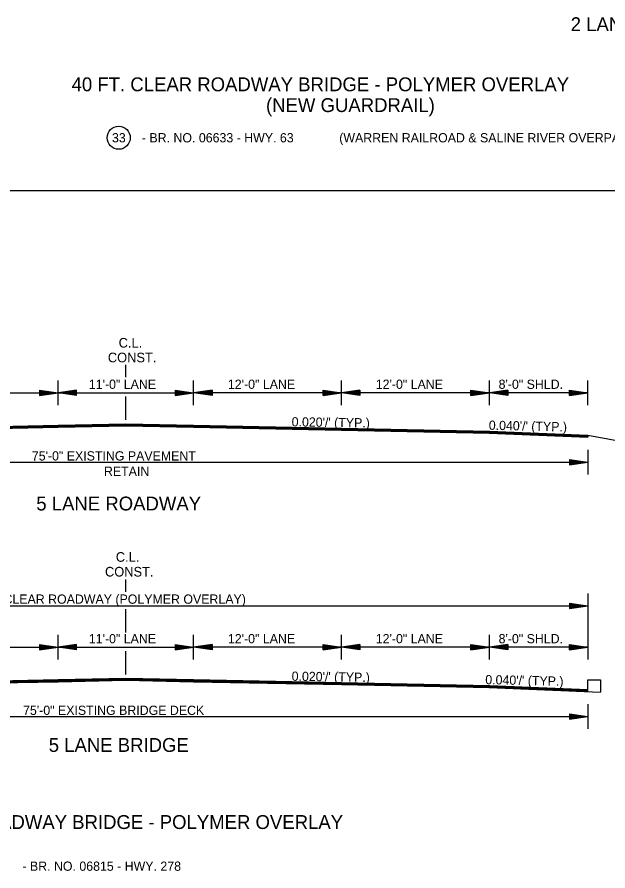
# Model space of a CAD drawing. Extents: x 545241 to 1930787, y -1971772 to 596640.
# Drawn here: x 547171 to 547650, y -1963938 to -1963245 of the extents above; entities that cross this region are included whole.
import ezdxf

# ---------------------------------------------------------------- set-up
doc = ezdxf.new("R2010")
doc.units = 0
doc.layers.add('R_Border', color=7, linetype='Continuous')
doc.layers.add('R_Draft', color=7, linetype='Continuous')

msp = doc.modelspace()

# ---------------------------------------------------------------- linework, layer by layer
at = {"layer": 'R_Border'}
for p, q in [((546745.07, -1963386.13), (547773.02, -1963386.13)), ((547634.04, -1963783.08), (547644.21, -1963783.08)), ((547634.04, -1963792.49), (547634.04, -1963783.08)), ((547644.21, -1963783.08), (547644.21, -1963793.07))]:
    msp.add_line(p, q, dxfattribs=at)
msp.add_circle((547253.23, -1963343.4), 9.34, dxfattribs=at)
at = {"layer": 'R_Draft'}
for p, q in [((547259.04, -1963537.63), (547259.04, -1963527.63)), ((547204.04, -1963560.29), (547204.04, -1963540.39)), ((547314.04, -1963560.29), (547314.04, -1963540.39)), ((547434.04, -1963560.29), (547434.04, -1963540.39)), ((547554.04, -1963560.29), (547554.04, -1963540.39)), ((547634.04, -1963560.29), (547634.04, -1963540.29)), ((547189.04, -1963548.04), (547204.04, -1963550.29)), ((547189.04, -1963548.04), (547189.04, -1963552.54)), ((547189.04, -1963548.41), (547201.54, -1963550.29)), ((547189.04, -1963548.79), (547198.96, -1963550.29)), ((547189.04, -1963549.17), (547196.46, -1963550.29)), ((547189.04, -1963549.56), (547193.92, -1963550.29)), ((547189.04, -1963549.93), (547191.41, -1963550.29)), ((547219.04, -1963548.04), (547204.04, -1963550.29)), ((547219.04, -1963548.41), (547206.55, -1963550.29)), ((547219.04, -1963548.79), (547209.13, -1963550.29)), ((547219.04, -1963549.17), (547211.63, -1963550.29)), ((547219.04, -1963549.55), (547214.17, -1963550.29)), ((547219.04, -1963549.93), (547216.67, -1963550.29)), ((547219.04, -1963552.54), (547219.04, -1963548.04)), ((547299.04, -1963548.04), (547314.04, -1963550.29)), ((547299.04, -1963548.04), (547299.04, -1963552.54)), ((547299.04, -1963548.41), (547311.54, -1963550.29)), ((547299.04, -1963548.79), (547308.96, -1963550.29)), ((547299.04, -1963549.17), (547306.46, -1963550.29)), ((547299.04, -1963549.56), (547303.92, -1963550.29)), ((547299.04, -1963549.93), (547301.41, -1963550.29)), ((547329.04, -1963548.04), (547314.04, -1963550.29)), ((547329.04, -1963548.41), (547316.55, -1963550.29)), ((547329.04, -1963548.79), (547319.13, -1963550.29)), ((547329.04, -1963549.17), (547321.63, -1963550.29)), ((547329.04, -1963549.56), (547324.17, -1963550.29)), ((547329.04, -1963549.93), (547326.67, -1963550.29)), ((547329.04, -1963548.04), (547329.04, -1963552.54)), ((547419.04, -1963548.04), (547434.04, -1963550.29)), ((547419.04, -1963552.54), (547419.04, -1963548.04)), ((547419.04, -1963548.41), (547431.54, -1963550.29)), ((547419.04, -1963548.79), (547428.96, -1963550.29)), ((547419.04, -1963549.17), (547426.46, -1963550.29)), ((547419.04, -1963549.55), (547423.92, -1963550.29)), ((547419.04, -1963549.93), (547421.41, -1963550.29)), ((547449.04, -1963548.04), (547434.04, -1963550.29)), ((547449.04, -1963548.41), (547436.55, -1963550.29)), ((547449.04, -1963548.79), (547439.13, -1963550.29)), ((547449.04, -1963549.17), (547441.63, -1963550.29)), ((547449.04, -1963549.56), (547444.17, -1963550.29)), ((547449.04, -1963549.93), (547446.67, -1963550.29)), ((547449.04, -1963548.04), (547449.04, -1963552.54)), ((547539.04, -1963548.04), (547554.04, -1963550.29)), ((547539.04, -1963552.54), (547539.04, -1963548.04)), ((547539.04, -1963548.41), (547551.54, -1963550.29)), ((547539.04, -1963548.79), (547548.96, -1963550.29)), ((547539.04, -1963549.17), (547546.46, -1963550.29)), ((547539.04, -1963549.55), (547543.92, -1963550.29)), ((547539.04, -1963549.93), (547541.41, -1963550.29)), ((547569.04, -1963548.04), (547554.04, -1963550.29)), ((547569.04, -1963548.41), (547556.55, -1963550.29)), ((547569.04, -1963548.79), (547559.13, -1963550.29)), ((547569.04, -1963549.17), (547561.63, -1963550.29)), ((547569.04, -1963549.56), (547564.17, -1963550.29)), ((547569.04, -1963549.93), (547566.67, -1963550.29)), ((547569.04, -1963548.04), (547569.04, -1963552.54)), ((547619.04, -1963548.04), (547634.04, -1963550.29)), ((547619.04, -1963552.54), (547619.04, -1963548.04)), ((547619.04, -1963548.41), (547631.54, -1963550.29)), ((547619.04, -1963548.79), (547628.96, -1963550.29)), ((547619.04, -1963549.17), (547626.46, -1963550.29)), ((547619.04, -1963549.55), (547623.92, -1963550.29)), ((547619.04, -1963549.93), (547621.41, -1963550.29)), ((547084.04, -1963550.29), (547204.04, -1963550.29)), ((547189.04, -1963552.54), (547204.04, -1963550.29)), ((547189.04, -1963551.02), (547193.92, -1963550.29)), ((547189.04, -1963551.78), (547198.96, -1963550.29)), ((547189.04, -1963552.16), (547201.54, -1963550.29)), ((547189.04, -1963551.4), (547196.46, -1963550.29)), ((547189.04, -1963550.64), (547191.41, -1963550.29)), ((547204.04, -1963550.29), (547314.04, -1963550.29)), ((547219.04, -1963552.54), (547204.04, -1963550.29)), ((547219.04, -1963552.16), (547206.55, -1963550.29)), ((547219.04, -1963551.78), (547209.13, -1963550.29)), ((547219.04, -1963551.4), (547211.63, -1963550.29)), ((547219.04, -1963551.01), (547214.17, -1963550.29)), ((547219.04, -1963550.64), (547216.67, -1963550.29)), ((547259.04, -1963572.34), (547259.04, -1963553.4)), ((547299.04, -1963552.54), (547314.04, -1963550.29)), ((547299.04, -1963551.02), (547303.92, -1963550.29)), ((547299.04, -1963551.78), (547308.96, -1963550.29)), ((547299.04, -1963552.16), (547311.54, -1963550.29)), ((547299.04, -1963551.4), (547306.46, -1963550.29)), ((547299.04, -1963550.64), (547301.41, -1963550.29)), ((547434.04, -1963550.29), (547314.04, -1963550.29)), ((547329.04, -1963552.54), (547314.04, -1963550.29)), ((547329.04, -1963552.16), (547316.55, -1963550.29)), ((547329.04, -1963551.78), (547319.13, -1963550.29)), ((547329.04, -1963551.4), (547321.63, -1963550.29)), ((547329.04, -1963551.02), (547324.17, -1963550.29)), ((547329.04, -1963550.64), (547326.67, -1963550.29)), ((547419.04, -1963552.54), (547434.04, -1963550.29)), ((547419.04, -1963551.01), (547423.92, -1963550.29)), ((547419.04, -1963551.78), (547428.96, -1963550.29)), ((547419.04, -1963552.16), (547431.54, -1963550.29)), ((547419.04, -1963551.4), (547426.46, -1963550.29)), ((547419.04, -1963550.64), (547421.41, -1963550.29)), ((547554.04, -1963550.29), (547434.04, -1963550.29)), ((547449.04, -1963552.54), (547434.04, -1963550.29)), ((547449.04, -1963552.16), (547436.55, -1963550.29)), ((547449.04, -1963551.78), (547439.13, -1963550.29)), ((547449.04, -1963551.4), (547441.63, -1963550.29)), ((547449.04, -1963551.02), (547444.17, -1963550.29)), ((547449.04, -1963550.64), (547446.67, -1963550.29)), ((547539.04, -1963552.54), (547554.04, -1963550.29)), ((547539.04, -1963551.01), (547543.92, -1963550.29)), ((547539.04, -1963551.78), (547548.96, -1963550.29)), ((547539.04, -1963552.16), (547551.54, -1963550.29)), ((547539.04, -1963551.4), (547546.46, -1963550.29)), ((547539.04, -1963550.64), (547541.41, -1963550.29)), ((547634.04, -1963550.29), (547554.04, -1963550.29)), ((547569.04, -1963552.54), (547554.04, -1963550.29)), ((547569.04, -1963552.16), (547556.55, -1963550.29)), ((547569.04, -1963551.78), (547559.13, -1963550.29)), ((547569.04, -1963551.4), (547561.63, -1963550.29)), ((547569.04, -1963551.02), (547564.17, -1963550.29)), ((547569.04, -1963550.64), (547566.67, -1963550.29)), ((547619.04, -1963552.54), (547634.04, -1963550.29)), ((547619.04, -1963551.01), (547623.92, -1963550.29)), ((547619.04, -1963551.78), (547628.96, -1963550.29)), ((547619.04, -1963552.16), (547631.54, -1963550.29)), ((547619.04, -1963551.4), (547626.46, -1963550.29)), ((547619.04, -1963550.64), (547621.41, -1963550.29)), ((547084.04, -1963578.99), (547204.04, -1963576.59)), ((547084.04, -1963579.29), (547204.04, -1963576.89)), ((547084.04, -1963579.59), (547204.04, -1963577.19)), ((547084.04, -1963579.89), (547204.04, -1963577.49)), ((547084.04, -1963580.19), (547204.04, -1963577.79)), ((547204.04, -1963576.59), (547259.04, -1963575.49)), ((547204.04, -1963576.89), (547259.04, -1963575.79)), ((547204.04, -1963577.19), (547259.04, -1963576.09)), ((547204.04, -1963577.49), (547259.04, -1963576.39)), ((547204.04, -1963577.79), (547259.04, -1963576.69)), ((547204.04, -1963578.09), (547259.04, -1963576.99)), ((547204.04, -1963578.26), (547259.04, -1963577.16)), ((547259.04, -1963575.49), (547314.04, -1963576.59)), ((547259.04, -1963575.79), (547314.04, -1963576.89)), ((547259.04, -1963576.09), (547314.04, -1963577.19)), ((547259.04, -1963576.39), (547314.04, -1963577.49)), ((547259.04, -1963576.69), (547314.04, -1963577.79)), ((547259.04, -1963576.99), (547314.04, -1963578.09)), ((547259.04, -1963577.16), (547314.04, -1963578.26)), ((547314.04, -1963576.59), (547434.04, -1963578.99)), ((547314.04, -1963576.89), (547434.04, -1963579.29)), ((547314.04, -1963577.19), (547434.04, -1963579.59)), ((547314.04, -1963577.49), (547434.04, -1963579.89)), ((547314.04, -1963577.79), (547434.04, -1963580.19)), ((547084.04, -1963580.49), (547204.04, -1963578.09)), ((547084.04, -1963580.66), (547204.04, -1963578.26)), ((547314.04, -1963578.09), (547434.04, -1963580.49)), ((547314.04, -1963578.26), (547434.04, -1963580.66)), ((547434.04, -1963578.99), (547554.04, -1963581.39)), ((547434.04, -1963579.29), (547554.04, -1963581.69)), ((547434.04, -1963579.59), (547554.04, -1963581.99)), ((547434.04, -1963579.89), (547554.04, -1963582.29)), ((547434.04, -1963580.19), (547554.04, -1963582.59)), ((547434.04, -1963580.49), (547554.04, -1963582.89)), ((547434.04, -1963580.66), (547554.04, -1963583.06)), ((547553.99, -1963583.06), (547634.04, -1963586.26)), ((547554, -1963582.89), (547634.04, -1963586.09)), ((547554.01, -1963582.59), (547634.04, -1963585.79)), ((547554.02, -1963582.29), (547634.04, -1963585.49)), ((547554.03, -1963581.69), (547634.04, -1963584.89)), ((547554.03, -1963581.99), (547634.04, -1963585.19)), ((547554.04, -1963581.39), (547634.04, -1963584.59)), ((547634.04, -1963584.59), (547634.04, -1963586.26)), ((547634.04, -1963584.59), (547734.11, -1963602.97)), ((547634.04, -1963596.63), (547634.04, -1963616.63)), ((547619.02, -1963604.3), (547634.02, -1963606.55)), ((547619.02, -1963604.3), (547619.02, -1963608.8)), ((547619.02, -1963604.68), (547631.51, -1963606.55)), ((547619.02, -1963605.06), (547628.93, -1963606.55)), ((547619.02, -1963605.43), (547626.44, -1963606.55)), ((546884.04, -1963606.55), (547634.04, -1963606.55)), ((547619.02, -1963605.82), (547623.89, -1963606.55)), ((547619.02, -1963606.2), (547621.39, -1963606.55)), ((547619.02, -1963608.8), (547634.02, -1963606.55)), ((547619.02, -1963607.29), (547623.89, -1963606.55)), ((547619.02, -1963608.04), (547628.93, -1963606.55)), ((547619.02, -1963608.43), (547631.51, -1963606.55)), ((547619.02, -1963607.67), (547626.44, -1963606.55)), ((547619.02, -1963606.9), (547621.39, -1963606.55)), ((547259.04, -1963711.67), (547259.04, -1963701.67)), ((547634.04, -1963713.15), (547634.04, -1963766.68)), ((546884.04, -1963723.15), (547634.04, -1963723.15)), ((547619.04, -1963720.9), (547634.04, -1963723.15)), ((547619.04, -1963720.9), (547619.04, -1963725.4)), ((547619.04, -1963721.27), (547631.54, -1963723.15)), ((547619.04, -1963721.65), (547628.96, -1963723.15)), ((547619.04, -1963722.03), (547626.46, -1963723.15)), ((547619.04, -1963722.42), (547623.92, -1963723.15)), ((547619.04, -1963722.79), (547621.41, -1963723.15)), ((547619.04, -1963725.4), (547634.04, -1963723.15)), ((547619.04, -1963723.88), (547623.92, -1963723.15)), ((547619.04, -1963724.64), (547628.96, -1963723.15)), ((547619.04, -1963725.02), (547631.54, -1963723.15)), ((547619.04, -1963724.26), (547626.46, -1963723.15)), ((547619.04, -1963723.5), (547621.41, -1963723.15)), ((547259.04, -1963744.67), (547259.04, -1963725.97)), ((547204.04, -1963766.68), (547204.04, -1963746.79)), ((547314.04, -1963766.68), (547314.04, -1963746.79)), ((547434.04, -1963766.68), (547434.04, -1963746.79)), ((547554.04, -1963766.68), (547554.04, -1963746.79)), ((547084.04, -1963756.68), (547204.04, -1963756.68)), ((547189.04, -1963754.43), (547204.04, -1963756.68)), ((547189.04, -1963754.43), (547189.04, -1963758.93)), ((547189.04, -1963754.81), (547201.54, -1963756.68)), ((547189.04, -1963755.19), (547198.96, -1963756.68)), ((547189.04, -1963755.57), (547196.46, -1963756.68)), ((547189.04, -1963755.96), (547193.92, -1963756.68)), ((547189.04, -1963756.33), (547191.41, -1963756.68)), ((547189.04, -1963758.93), (547204.04, -1963756.68)), ((547189.04, -1963757.42), (547193.92, -1963756.68)), ((547189.04, -1963758.18), (547198.96, -1963756.68)), ((547189.04, -1963758.56), (547201.54, -1963756.68)), ((547189.04, -1963757.8), (547196.46, -1963756.68)), ((547189.04, -1963757.04), (547191.41, -1963756.68)), ((547219.04, -1963754.43), (547204.04, -1963756.68)), ((547204.04, -1963756.68), (547314.04, -1963756.68)), ((547219.04, -1963758.93), (547204.04, -1963756.68)), ((547219.04, -1963754.81), (547206.55, -1963756.68)), ((547219.04, -1963758.56), (547206.55, -1963756.68)), ((547219.04, -1963755.19), (547209.13, -1963756.68)), ((547219.04, -1963758.18), (547209.13, -1963756.68)), ((547219.04, -1963755.57), (547211.63, -1963756.68)), ((547219.04, -1963757.8), (547211.63, -1963756.68)), ((547219.04, -1963755.95), (547214.17, -1963756.68)), ((547219.04, -1963757.41), (547214.17, -1963756.68)), ((547219.04, -1963756.33), (547216.67, -1963756.68)), ((547219.04, -1963757.04), (547216.67, -1963756.68)), ((547219.04, -1963758.93), (547219.04, -1963754.43)), ((547299.04, -1963754.43), (547314.04, -1963756.68)), ((547299.04, -1963754.43), (547299.04, -1963758.93)), ((547299.04, -1963754.81), (547311.54, -1963756.68)), ((547299.04, -1963755.19), (547308.96, -1963756.68)), ((547299.04, -1963755.57), (547306.46, -1963756.68)), ((547299.04, -1963755.96), (547303.92, -1963756.68)), ((547299.04, -1963756.33), (547301.41, -1963756.68)), ((547299.04, -1963758.93), (547314.04, -1963756.68)), ((547299.04, -1963757.42), (547303.92, -1963756.68)), ((547299.04, -1963758.18), (547308.96, -1963756.68)), ((547299.04, -1963758.56), (547311.54, -1963756.68)), ((547299.04, -1963757.8), (547306.46, -1963756.68)), ((547299.04, -1963757.04), (547301.41, -1963756.68)), ((547329.04, -1963754.43), (547314.04, -1963756.68)), ((547434.04, -1963756.68), (547314.04, -1963756.68)), ((547329.04, -1963758.93), (547314.04, -1963756.68)), ((547329.04, -1963754.81), (547316.55, -1963756.68)), ((547329.04, -1963758.56), (547316.55, -1963756.68)), ((547329.04, -1963755.19), (547319.13, -1963756.68)), ((547329.04, -1963758.18), (547319.13, -1963756.68)), ((547329.04, -1963755.57), (547321.63, -1963756.68)), ((547329.04, -1963757.8), (547321.63, -1963756.68)), ((547329.04, -1963755.96), (547324.17, -1963756.68)), ((547329.04, -1963757.42), (547324.17, -1963756.68)), ((547329.04, -1963756.33), (547326.67, -1963756.68)), ((547329.04, -1963757.04), (547326.67, -1963756.68)), ((547329.04, -1963754.43), (547329.04, -1963758.93)), ((547419.04, -1963754.43), (547434.04, -1963756.68)), ((547419.04, -1963758.93), (547419.04, -1963754.43)), ((547419.04, -1963754.81), (547431.54, -1963756.68)), ((547419.04, -1963755.19), (547428.96, -1963756.68)), ((547419.04, -1963755.57), (547426.46, -1963756.68)), ((547419.04, -1963755.95), (547423.92, -1963756.68)), ((547419.04, -1963756.33), (547421.41, -1963756.68)), ((547419.04, -1963758.93), (547434.04, -1963756.68)), ((547419.04, -1963757.41), (547423.92, -1963756.68)), ((547419.04, -1963758.18), (547428.96, -1963756.68)), ((547419.04, -1963758.56), (547431.54, -1963756.68)), ((547419.04, -1963757.8), (547426.46, -1963756.68)), ((547419.04, -1963757.04), (547421.41, -1963756.68)), ((547449.04, -1963754.43), (547434.04, -1963756.68)), ((547554.04, -1963756.68), (547434.04, -1963756.68)), ((547449.04, -1963758.93), (547434.04, -1963756.68)), ((547449.04, -1963754.81), (547436.55, -1963756.68)), ((547449.04, -1963758.56), (547436.55, -1963756.68)), ((547449.04, -1963755.19), (547439.13, -1963756.68)), ((547449.04, -1963758.18), (547439.13, -1963756.68)), ((547449.04, -1963755.57), (547441.63, -1963756.68)), ((547449.04, -1963757.8), (547441.63, -1963756.68)), ((547449.04, -1963755.96), (547444.17, -1963756.68)), ((547449.04, -1963757.42), (547444.17, -1963756.68)), ((547449.04, -1963756.33), (547446.67, -1963756.68)), ((547449.04, -1963757.04), (547446.67, -1963756.68)), ((547449.04, -1963754.43), (547449.04, -1963758.93)), ((547539.04, -1963754.43), (547554.04, -1963756.68)), ((547539.04, -1963758.93), (547539.04, -1963754.43)), ((547539.04, -1963754.81), (547551.54, -1963756.68)), ((547539.04, -1963755.19), (547548.96, -1963756.68)), ((547539.04, -1963755.57), (547546.46, -1963756.68)), ((547539.04, -1963755.95), (547543.92, -1963756.68)), ((547539.04, -1963756.33), (547541.41, -1963756.68)), ((547539.04, -1963758.93), (547554.04, -1963756.68)), ((547539.04, -1963757.41), (547543.92, -1963756.68)), ((547539.04, -1963758.18), (547548.96, -1963756.68)), ((547539.04, -1963758.56), (547551.54, -1963756.68)), ((547539.04, -1963757.8), (547546.46, -1963756.68)), ((547539.04, -1963757.04), (547541.41, -1963756.68)), ((547569.04, -1963754.43), (547554.04, -1963756.68)), ((547634.04, -1963756.68), (547554.04, -1963756.68)), ((547569.04, -1963758.93), (547554.04, -1963756.68)), ((547569.04, -1963754.81), (547556.55, -1963756.68)), ((547569.04, -1963758.56), (547556.55, -1963756.68)), ((547569.04, -1963755.19), (547559.13, -1963756.68)), ((547569.04, -1963758.18), (547559.13, -1963756.68)), ((547569.04, -1963755.57), (547561.63, -1963756.68)), ((547569.04, -1963757.8), (547561.63, -1963756.68)), ((547569.04, -1963755.96), (547564.17, -1963756.68)), ((547569.04, -1963757.42), (547564.17, -1963756.68)), ((547569.04, -1963756.33), (547566.67, -1963756.68)), ((547569.04, -1963757.04), (547566.67, -1963756.68)), ((547569.04, -1963754.43), (547569.04, -1963758.93)), ((547619.04, -1963754.43), (547634.04, -1963756.68)), ((547619.04, -1963758.93), (547619.04, -1963754.43)), ((547619.04, -1963754.81), (547631.54, -1963756.68)), ((547619.04, -1963755.19), (547628.96, -1963756.68)), ((547619.04, -1963755.57), (547626.46, -1963756.68)), ((547619.04, -1963755.95), (547623.92, -1963756.68)), ((547619.04, -1963756.33), (547621.41, -1963756.68)), ((547619.04, -1963758.93), (547634.04, -1963756.68)), ((547619.04, -1963757.41), (547623.92, -1963756.68)), ((547619.04, -1963758.18), (547628.96, -1963756.68)), ((547619.04, -1963758.56), (547631.54, -1963756.68)), ((547619.04, -1963757.8), (547626.46, -1963756.68)), ((547619.04, -1963757.04), (547621.41, -1963756.68)), ((547259.04, -1963778.74), (547259.04, -1963759.8)), ((547084.04, -1963785.39), (547204.04, -1963782.99)), ((547084.04, -1963785.69), (547204.04, -1963783.29)), ((547084.04, -1963785.99), (547204.04, -1963783.59)), ((547084.04, -1963786.29), (547204.04, -1963783.89)), ((547084.04, -1963786.59), (547204.04, -1963784.19)), ((547084.04, -1963786.89), (547204.04, -1963784.49)), ((547084.04, -1963787.06), (547204.04, -1963784.66)), ((547204.04, -1963782.99), (547259.04, -1963781.89)), ((547204.04, -1963783.29), (547259.04, -1963782.19)), ((547204.04, -1963783.59), (547259.04, -1963782.49)), ((547204.04, -1963783.89), (547259.04, -1963782.79)), ((547204.04, -1963784.19), (547259.04, -1963783.09)), ((547204.04, -1963784.49), (547259.04, -1963783.39)), ((547204.04, -1963784.66), (547259.04, -1963783.56)), ((547259.04, -1963781.89), (547314.04, -1963782.99)), ((547259.04, -1963782.19), (547314.04, -1963783.29)), ((547259.04, -1963782.49), (547314.04, -1963783.59)), ((547259.04, -1963782.79), (547314.04, -1963783.89)), ((547259.04, -1963783.09), (547314.04, -1963784.19)), ((547259.04, -1963783.39), (547314.04, -1963784.49)), ((547259.04, -1963783.56), (547314.04, -1963784.66)), ((547314.04, -1963782.99), (547434.04, -1963785.39)), ((547314.04, -1963783.29), (547434.04, -1963785.69)), ((547314.04, -1963783.59), (547434.04, -1963785.99)), ((547314.04, -1963783.89), (547434.04, -1963786.29)), ((547314.04, -1963784.19), (547434.04, -1963786.59)), ((547314.04, -1963784.49), (547434.04, -1963786.89)), ((547314.04, -1963784.66), (547434.04, -1963787.06)), ((547434.04, -1963785.39), (547554.04, -1963787.79)), ((547434.04, -1963785.69), (547554.04, -1963788.09)), ((547434.04, -1963785.99), (547554.04, -1963788.39)), ((547434.04, -1963786.29), (547554.04, -1963788.69)), ((547434.04, -1963786.59), (547554.04, -1963788.99)), ((547434.04, -1963786.89), (547554.04, -1963789.29)), ((547434.04, -1963787.06), (547554.04, -1963789.46)), ((547553.99, -1963789.46), (547644.21, -1963793.07)), ((547554, -1963789.29), (547634.04, -1963792.49)), ((547554.01, -1963788.99), (547634.04, -1963792.19)), ((547554.02, -1963788.69), (547634.04, -1963791.89)), ((547554.03, -1963788.09), (547634.04, -1963791.29)), ((547554.03, -1963788.39), (547634.04, -1963791.59)), ((547554.04, -1963787.79), (547634.04, -1963790.99)), ((547634.04, -1963803.02), (547634.04, -1963823.02)), ((546884.04, -1963812.95), (547634.04, -1963812.95)), ((547619.02, -1963810.7), (547634.02, -1963812.95)), ((547619.02, -1963810.7), (547619.02, -1963815.2)), ((547619.02, -1963811.07), (547631.51, -1963812.95)), ((547619.02, -1963811.45), (547628.93, -1963812.95)), ((547619.02, -1963811.83), (547626.44, -1963812.95)), ((547619.02, -1963812.22), (547623.89, -1963812.95)), ((547619.02, -1963812.59), (547621.39, -1963812.95)), ((547619.02, -1963815.2), (547634.02, -1963812.95)), ((547619.02, -1963813.68), (547623.89, -1963812.95)), ((547619.02, -1963814.44), (547628.93, -1963812.95)), ((547619.02, -1963814.82), (547631.51, -1963812.95)), ((547619.02, -1963814.06), (547626.44, -1963812.95)), ((547619.02, -1963813.3), (547621.39, -1963812.95))]:
    msp.add_line(p, q, dxfattribs=at)

# ---------------------------------------------------------------- texts
for s, height, p in [('2 LANE BRIDGE - RAILROAD OVERPASS', 11.25, (547620.07, -1963256.91)), ('40 FT. CLEAR ROADWAY BRIDGE - POLYMER OVERLAY', 11.25, (547214.98, -1963305.67)), ('(NEW GUARDRAIL)', 11.25, (547372.75, -1963322.54)), ('33', 7.5, (547247.74, -1963347.15)), ('- BR. NO. 06633 - HWY. 63', 7.5, (547272.03, -1963347.15)), ('(WARREN RAILROAD & SALINE RIVER OVERPASS)', 7.5, (547432.23, -1963347.15)), ('C.L.', 7.8, (547253.18, -1963513.61)), ('CONST.', 7.8, (547244.4, -1963525.57)), ('11\'-0" LANE', 7.5, (547228.98, -1963547.11)), ('12\'-0" LANE', 7.5, (547341.86, -1963547.11)), ('12\'-0" LANE', 7.5, (547461.86, -1963547.11)), ('8\'-0" SHLD.', 7.5, (547561.56, -1963547.11)), ('75\'-0" EXISTING PAVEMENT', 7.5, (547182.71, -1963605.23)), ('RETAIN', 7.5, (547241.24, -1963617.72)), ('5 LANE ROADWAY', 11.25, (547186.32, -1963645.77)), ('C.L.', 7.8, (547250.86, -1963687.39)), ('CONST.', 7.8, (547242.07, -1963699.35)), ('75\'-0" CLEAR ROADWAY (POLYMER OVERLAY)', 7.5, (547131.37, -1963721.43)), ('11\'-0" LANE', 7.5, (547228.98, -1963753.51)), ('12\'-0" LANE', 7.5, (547341.86, -1963753.51)), ('12\'-0" LANE', 7.5, (547461.86, -1963753.51)), ('8\'-0" SHLD.', 7.5, (547561.56, -1963753.51)), ('75\'-0" EXISTING BRIDGE DECK', 7.5, (547175.6, -1963811.62)), ('5 LANE BRIDGE', 11.25, (547196.42, -1963841.62)), ('75 FT. CLEAR ROADWAY BRIDGE - POLYMER OVERLAY', 11.25, (547031.56, -1963904.17)), ('- BR. NO. 06815 - HWY. 278', 7.5, (547175.03, -1963938.08))]:
    msp.add_text(s, height=height, dxfattribs=at).set_placement(p)
for s, rotation, p in [("0.020'/' (TYP.)", 359.12809, (547393.54, -1963577.53)), ("0.040'/' (TYP.)", 358.68162, (547553.54, -1963580.27)), ("0.020'/' (TYP.)", 359.12809, (547393.54, -1963783.93)), ("0.040'/' (TYP.)", 358.68162, (547550.68, -1963786.67))]:
    msp.add_text(s, height=7.5, rotation=rotation, dxfattribs=at).set_placement(p)

doc.saveas('drawing.dxf')
